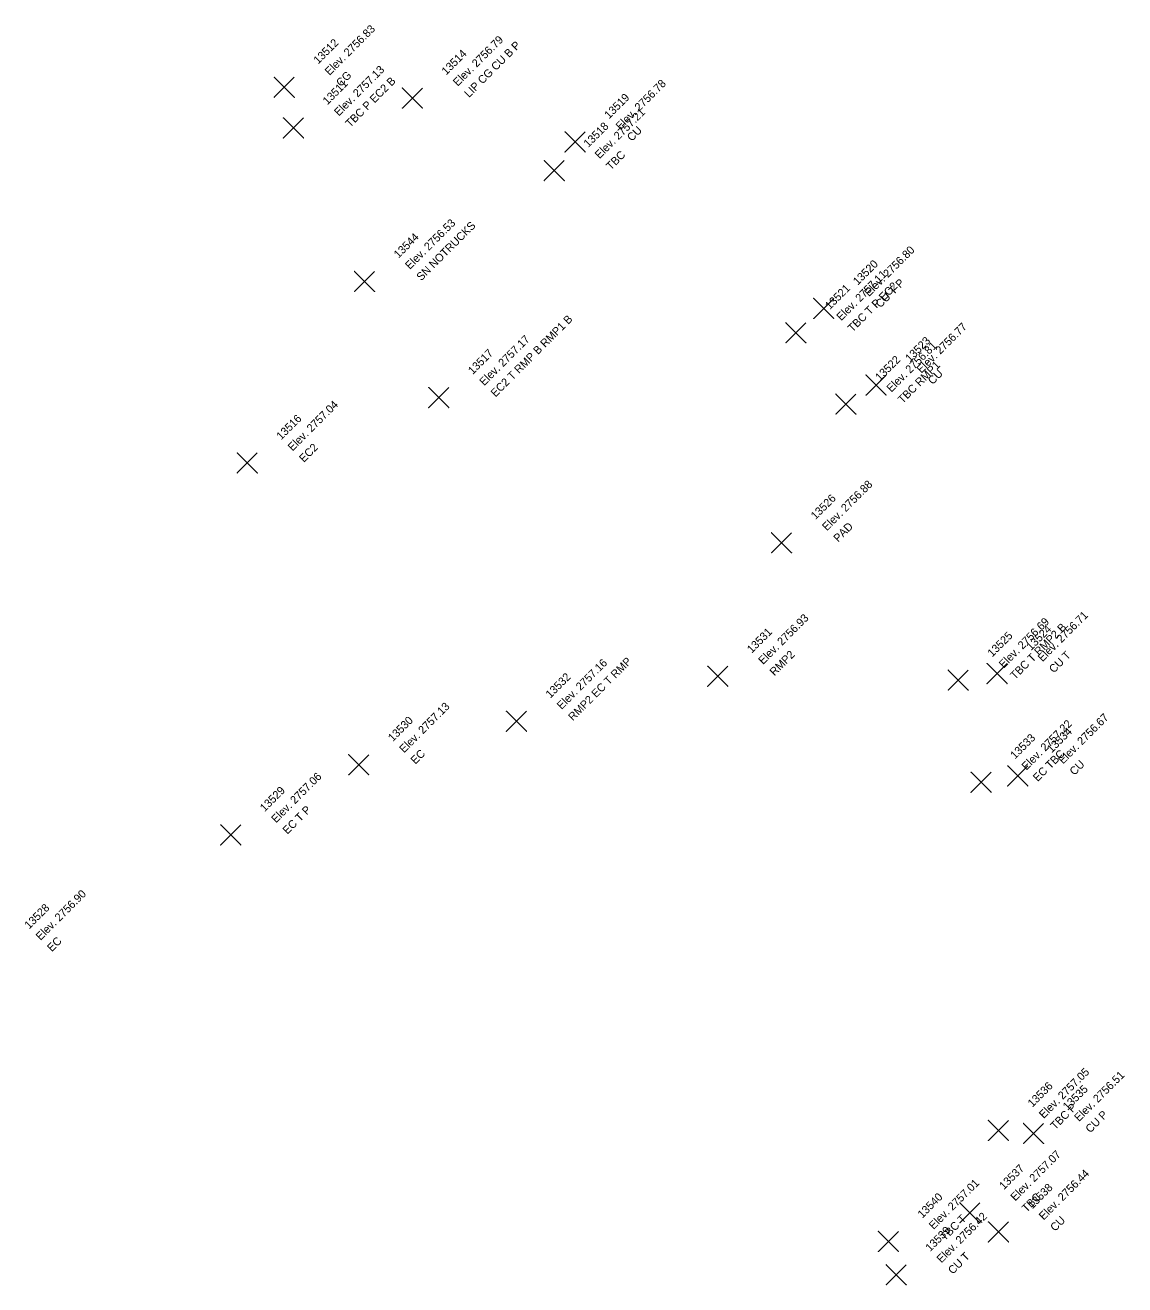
# Model space of a CAD drawing. Extents: x 2493999 to 2503109, y 700767 to 706646.
# Drawn here: x 2502335.97 to 2502352.46, y 703164.22 to 703183.11 of the extents above; entities that cross this region are included whole.
import ezdxf

# ---------------------------------------------------------------- set-up
doc = ezdxf.new("R2010")
doc.units = 0
doc.layers.add('ALG_CL_BLUE_Horiz', color=7, linetype='Continuous')
doc.layers.add('DES_SURFACE_Existing-Ground', color=7, linetype='Continuous')

msp = doc.modelspace()

# ---------------------------------------------------------------- linework, layer by layer
at = {"layer": 'ALG_CL_BLUE_Horiz'}
for points in [[(2502339.858, 703182.183), (2502339.708, 703182.333), (2502339.858, 703182.183), (2502339.708, 703182.033), (2502339.858, 703182.183), (2502340.008, 703182.033), (2502339.858, 703182.183), (2502340.008, 703182.333)], [(2502341.779, 703182.02), (2502341.629, 703182.17), (2502341.779, 703182.02), (2502341.629, 703181.87), (2502341.779, 703182.02), (2502341.929, 703181.87), (2502341.779, 703182.02), (2502341.929, 703182.17)], [(2502339.996, 703181.572), (2502339.846, 703181.722), (2502339.996, 703181.572), (2502339.846, 703181.422), (2502339.996, 703181.572), (2502340.146, 703181.422), (2502339.996, 703181.572), (2502340.146, 703181.722)], [(2502344.219, 703181.363), (2502344.069, 703181.513), (2502344.219, 703181.363), (2502344.069, 703181.213), (2502344.219, 703181.363), (2502344.369, 703181.213), (2502344.219, 703181.363), (2502344.369, 703181.513)], [(2502343.907, 703180.932), (2502343.757, 703181.082), (2502343.907, 703180.932), (2502343.757, 703180.782), (2502343.907, 703180.932), (2502344.057, 703180.782), (2502343.907, 703180.932), (2502344.057, 703181.082)], [(2502341.062, 703179.271), (2502340.912, 703179.421), (2502341.062, 703179.271), (2502340.912, 703179.121), (2502341.062, 703179.271), (2502341.212, 703179.121), (2502341.062, 703179.271), (2502341.212, 703179.421)], [(2502347.947, 703178.866), (2502347.797, 703179.016), (2502347.947, 703178.866), (2502347.797, 703178.716), (2502347.947, 703178.866), (2502348.097, 703178.716), (2502347.947, 703178.866), (2502348.097, 703179.016)], [(2502347.529, 703178.501), (2502347.379, 703178.651), (2502347.529, 703178.501), (2502347.379, 703178.351), (2502347.529, 703178.501), (2502347.679, 703178.351), (2502347.529, 703178.501), (2502347.679, 703178.651)], [(2502348.731, 703177.715), (2502348.581, 703177.865), (2502348.731, 703177.715), (2502348.581, 703177.565), (2502348.731, 703177.715), (2502348.881, 703177.565), (2502348.731, 703177.715), (2502348.881, 703177.865)], [(2502342.175, 703177.528), (2502342.025, 703177.678), (2502342.175, 703177.528), (2502342.025, 703177.378), (2502342.175, 703177.528), (2502342.325, 703177.378), (2502342.175, 703177.528), (2502342.325, 703177.678)], [(2502348.28, 703177.43), (2502348.13, 703177.58), (2502348.28, 703177.43), (2502348.13, 703177.28), (2502348.28, 703177.43), (2502348.43, 703177.28), (2502348.28, 703177.43), (2502348.43, 703177.58)], [(2502339.303, 703176.547), (2502339.153, 703176.697), (2502339.303, 703176.547), (2502339.153, 703176.397), (2502339.303, 703176.547), (2502339.453, 703176.397), (2502339.303, 703176.547), (2502339.453, 703176.697)], [(2502347.315, 703175.351), (2502347.165, 703175.501), (2502347.315, 703175.351), (2502347.165, 703175.201), (2502347.315, 703175.351), (2502347.465, 703175.201), (2502347.315, 703175.351), (2502347.465, 703175.501)], [(2502346.358, 703173.347), (2502346.208, 703173.497), (2502346.358, 703173.347), (2502346.208, 703173.197), (2502346.358, 703173.347), (2502346.508, 703173.197), (2502346.358, 703173.347), (2502346.508, 703173.497)], [(2502349.965, 703173.291), (2502349.815, 703173.441), (2502349.965, 703173.291), (2502349.815, 703173.141), (2502349.965, 703173.291), (2502350.115, 703173.141), (2502349.965, 703173.291), (2502350.115, 703173.441)], [(2502350.547, 703173.388), (2502350.397, 703173.538), (2502350.547, 703173.388), (2502350.397, 703173.238), (2502350.547, 703173.388), (2502350.697, 703173.238), (2502350.547, 703173.388), (2502350.697, 703173.538)], [(2502343.338, 703172.672), (2502343.188, 703172.822), (2502343.338, 703172.672), (2502343.188, 703172.522), (2502343.338, 703172.672), (2502343.488, 703172.522), (2502343.338, 703172.672), (2502343.488, 703172.822)], [(2502340.975, 703172.02), (2502340.825, 703172.17), (2502340.975, 703172.02), (2502340.825, 703171.87), (2502340.975, 703172.02), (2502341.125, 703171.87), (2502340.975, 703172.02), (2502341.125, 703172.17)], [(2502350.856, 703171.853), (2502350.706, 703172.003), (2502350.856, 703171.853), (2502350.706, 703171.703), (2502350.856, 703171.853), (2502351.006, 703171.703), (2502350.856, 703171.853), (2502351.006, 703172.003)], [(2502350.306, 703171.759), (2502350.156, 703171.909), (2502350.306, 703171.759), (2502350.156, 703171.609), (2502350.306, 703171.759), (2502350.456, 703171.609), (2502350.306, 703171.759), (2502350.456, 703171.909)], [(2502339.055, 703170.969), (2502338.905, 703171.119), (2502339.055, 703170.969), (2502338.905, 703170.819), (2502339.055, 703170.969), (2502339.205, 703170.819), (2502339.055, 703170.969), (2502339.205, 703171.119)], [(2502350.567, 703166.537), (2502350.417, 703166.687), (2502350.567, 703166.537), (2502350.417, 703166.387), (2502350.567, 703166.537), (2502350.717, 703166.387), (2502350.567, 703166.537), (2502350.717, 703166.687)], [(2502351.094, 703166.49), (2502350.944, 703166.64), (2502351.094, 703166.49), (2502350.944, 703166.34), (2502351.094, 703166.49), (2502351.244, 703166.34), (2502351.094, 703166.49), (2502351.244, 703166.64)], [(2502350.139, 703165.3), (2502349.989, 703165.45), (2502350.139, 703165.3), (2502349.989, 703165.15), (2502350.139, 703165.3), (2502350.289, 703165.15), (2502350.139, 703165.3), (2502350.289, 703165.45)], [(2502350.566, 703165.013), (2502350.416, 703165.163), (2502350.566, 703165.013), (2502350.416, 703164.863), (2502350.566, 703165.013), (2502350.716, 703164.863), (2502350.566, 703165.013), (2502350.716, 703165.163)], [(2502348.916, 703164.872), (2502348.766, 703165.022), (2502348.916, 703164.872), (2502348.766, 703164.722), (2502348.916, 703164.872), (2502349.066, 703164.722), (2502348.916, 703164.872), (2502349.066, 703165.022)], [(2502349.033, 703164.37), (2502348.883, 703164.52), (2502349.033, 703164.37), (2502348.883, 703164.22), (2502349.033, 703164.37), (2502349.183, 703164.22), (2502349.033, 703164.37), (2502349.183, 703164.52)]]:
    msp.add_lwpolyline(points, dxfattribs=at)

# ---------------------------------------------------------------- texts
at = {"layer": 'DES_SURFACE_Existing-Ground'}
for s, p in [('Elev. 2756.83', (2502340.537, 703182.353)), ('13512', (2502340.367, 703182.522)), ('Elev. 2756.79', (2502342.458, 703182.19)), ('13514', (2502342.288, 703182.359)), ('LIP CG CU B P', (2502342.628, 703182.02)), ('Elev. 2757.13', (2502340.675, 703181.742)), ('CG', (2502340.707, 703182.183)), ('TBC P EC2 B', (2502340.845, 703181.572)), ('13511', (2502340.505, 703181.911)), ('Elev. 2756.78', (2502344.898, 703181.533)), ('13519', (2502344.728, 703181.702)), ('Elev. 2757.21', (2502344.586, 703181.102)), ('13518', (2502344.416, 703181.271)), ('CU', (2502345.068, 703181.363)), ('TBC', (2502344.756, 703180.932)), ('Elev. 2756.53', (2502341.741, 703179.441)), ('SN NOTRUCKS', (2502341.911, 703179.271)), ('13544', (2502341.571, 703179.61)), ('Elev. 2756.80', (2502348.626, 703179.036)), ('13520', (2502348.456, 703179.205)), ('Elev. 2757.11', (2502348.208, 703178.671)), ('CU T P', (2502348.796, 703178.866)), ('13521', (2502348.038, 703178.84)), ('TBC T P EC2', (2502348.378, 703178.501)), ('EC2 T RMP B RMP1 B', (2502343.024, 703177.528)), ('Elev. 2756.77', (2502349.41, 703177.885)), ('Elev. 2757.17', (2502342.854, 703177.698)), ('Elev. 2756.81', (2502348.959, 703177.6)), ('13523', (2502349.24, 703178.054)), ('13517', (2502342.684, 703177.867)), ('13522', (2502348.789, 703177.769)), ('TBC RMP1', (2502349.129, 703177.43)), ('CU', (2502349.58, 703177.715)), ('Elev. 2757.04', (2502339.982, 703176.717)), ('13516', (2502339.812, 703176.886)), ('EC2', (2502340.152, 703176.547)), ('Elev. 2756.88', (2502347.994, 703175.521)), ('13526', (2502347.824, 703175.69)), ('PAD', (2502348.164, 703175.351)), ('Elev. 2756.93', (2502347.037, 703173.517)), ('Elev. 2756.69', (2502350.644, 703173.461)), ('Elev. 2756.71', (2502351.226, 703173.558)), ('13531', (2502346.867, 703173.686)), ('13525', (2502350.474, 703173.63)), ('TBC T RMP2 B', (2502350.814, 703173.291)), ('13524', (2502351.056, 703173.727)), ('RMP2 EC T RMP', (2502344.187, 703172.672)), ('RMP2', (2502347.207, 703173.347)), ('CU T', (2502351.396, 703173.388)), ('Elev. 2757.16', (2502344.017, 703172.842)), ('13532', (2502343.847, 703173.011)), ('Elev. 2757.13', (2502341.654, 703172.19)), ('13530', (2502341.484, 703172.359)), ('Elev. 2757.22', (2502350.985, 703171.929)), ('Elev. 2756.67', (2502351.535, 703172.023)), ('13534', (2502351.365, 703172.192)), ('13533', (2502350.815, 703172.098)), ('EC', (2502341.824, 703172.02)), ('EC TBC', (2502351.155, 703171.759)), ('CU', (2502351.705, 703171.853)), ('Elev. 2757.06', (2502339.734, 703171.139)), ('13529', (2502339.564, 703171.308)), ('EC T P', (2502339.904, 703170.969)), ('Elev. 2756.90', (2502336.203, 703169.379)), ('13528', (2502336.033, 703169.548)), ('EC', (2502336.373, 703169.209)), ('Elev. 2757.05', (2502351.246, 703166.707)), ('Elev. 2756.51', (2502351.773, 703166.66)), ('13536', (2502351.076, 703166.876)), ('13535', (2502351.603, 703166.829)), ('TBC P', (2502351.416, 703166.537)), ('CU P', (2502351.943, 703166.49)), ('Elev. 2757.07', (2502350.818, 703165.47)), ('13537', (2502350.648, 703165.639)), ('Elev. 2756.44', (2502351.245, 703165.183)), ('Elev. 2757.01', (2502349.595, 703165.042)), ('13538', (2502351.075, 703165.352)), ('13540', (2502349.425, 703165.211)), ('TBC', (2502350.988, 703165.3)), ('Elev. 2756.42', (2502349.712, 703164.54)), ('TBC T', (2502349.765, 703164.872)), ('CU', (2502351.415, 703165.013)), ('13539', (2502349.542, 703164.709)), ('CU T', (2502349.882, 703164.37))]:
    msp.add_text(s, height=0.12, rotation=45, dxfattribs=at).set_placement(p)

doc.saveas('drawing.dxf')
